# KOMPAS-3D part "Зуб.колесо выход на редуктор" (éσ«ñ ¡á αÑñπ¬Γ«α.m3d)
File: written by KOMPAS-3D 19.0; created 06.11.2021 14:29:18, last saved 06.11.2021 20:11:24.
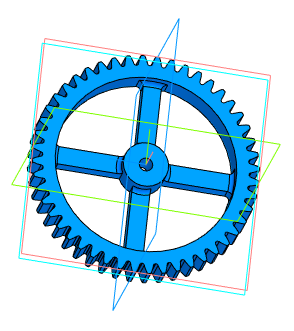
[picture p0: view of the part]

Document properties: Полное имя файла: D:\3D_print\3D проекты Компас 3D\Редуктор (Снова)\Вход на редуктор.m3d

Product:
- Part/product: Зуб.колесо выход на редуктор
    Материал: АБС 0603Т ТУ 2214-019-002 03521-96 (density 0 kg/m3)

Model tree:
1. ЛСК (Шестерня цилиндрическая с внешними зубьями):1  (with: Шестерня цилиндрическая с внешними зубьями:1, Плоскость XY, Плоскость ZX, Плоскость ZY, Ось X, Ось Y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)  (labels: &Фаска (Шестерня цилиндрическая с внешними зубьями):1)
     Ось X. X = 1; Ось Y. Y = 1; Ось Z. Z = 1; Угол 1 = 360
2. Эскиз для винтовой линии (Шестерня цилиндрическая с внешними зубьями):1  (with: Винтовая линия (Шестерня цилиндрическая с внешними зубьями):1, Шестерня цилиндрическая с внешними зубьями:1, Впадина (Шестерня цилиндрическая с внешними зубьями):1, Впадина прямая (Шестерня цилиндрическая с внешними зубьями):1, Массив косых впадин (Шестерня цилиндрическая с внешними зубьями):1)  (2 pattern instances)
     Число витков = 0.00346782; Смещение 2 = 6
3. Впадина прямая (Шестерня цилиндрическая с внешними зубьями):1  (39 pattern instances)
4. Впадина (Шестерня цилиндрическая с внешними зубьями):1  (with: Массив прямых впадин (Шестерня цилиндрическая с внешними зубьями):1, Шестерня цилиндрическая с внешними зубьями:1)  (9 pattern instances)
     N 1 = 1; Шаг 1 = 1; Номер 1 = 1
5. Впадина косая (Шестерня цилиндрическая с внешними зубьями):1  (with: Винтовая линия (Шестерня цилиндрическая с внешними зубьями):1, Впадина прямая (Шестерня цилиндрическая с внешними зубьями):1)  (46 pattern instances)
     N 1 = 1; Шаг 1 = 1; Номер 1 = 1
6. Шестерня цилиндрическая с внешними зубьями:1
7. Эскиз:1  (with: Цилиндр (Шестерня цилиндрическая с внешними зубьями):1, Впадина (Шестерня цилиндрическая с внешними зубьями):1)
8. Элемент выдавливания:1
9. Средняя плоскость:1  (with: Цилиндр (Шестерня цилиндрическая с внешними зубьями):1)
10. Эскиз:2  (with: Цилиндр (Шестерня цилиндрическая с внешними зубьями):1, Элемент выдавливания:1)
11. Элемент выдавливания:2
     Расстояние 2 = 3
12. Эскиз:3  (with: Элемент выдавливания:2)
13. Элемент выдавливания:3
14. Скругление:1  (with: Элемент выдавливания:3)
     Радиус = 1
15. Скругление:2  (with: Элемент выдавливания:2)
     Радиус = 1
16. Скругление:3  (with: Элемент выдавливания:2)  (labels: АБС 0603Т ТУ 2214-019-002 03521-96)
     Радиус = 1

Expressions: (VGExtS_1_z*VGExtS_1_M)/COSD(VGExtS_1_Beta); 360/VGExtS_1_z
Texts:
  SHAFT3D
  Количество отображаемых зубьев
  Угол наклона линии зубьев
  Шаг по кольцевому направлению
  (VGExtS_1_Beta>0)?(M_PI*VGExtS_1_z*VGExtS_1_M/SIND(VGExtS_1_Beta)):1000
  (VGExtS_1_Da<=0||VGExtS_1_Da>5e+7)?25:VGExtS_1_Da
  (VGExtS_1_H<=0||VGExtS_1_H>5e+7)?25:VGExtS_1_H
  VGExtS_1_zz<VGExtS_1_z?(VGExtS_1_zz+1):VGExtS_1_z
  (VGExtS_1_zz<=0||VGExtS_1==1)||(VGExtS_1_Beta>0)?1:0
  (VGExtS_1_zz<=0||VGExtS_1==1)||(VGExtS_1_Beta<=0)?1:0
  (VGExtS_1==1)||(VGExtS_1_Beta<=0)?1:0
